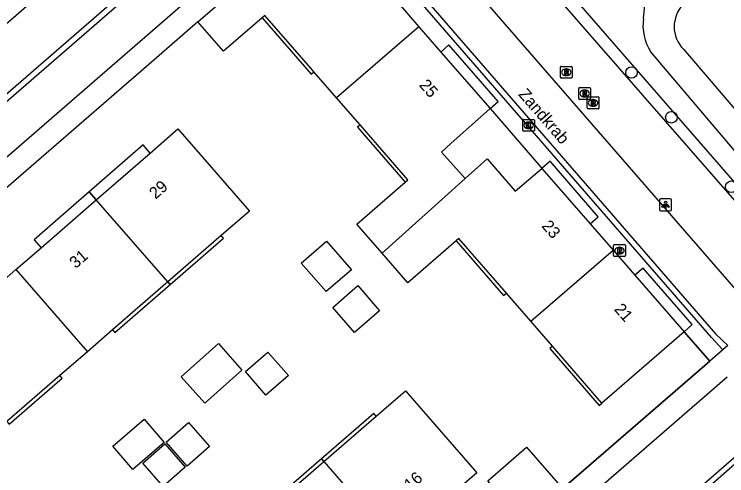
# Model space of a CAD drawing. Extents: x 155888 to 156864, y 383882 to 384671.
# Drawn here: x 156475 to 156535.1, y 384408.3 to 384447.4 of the extents above; entities that cross this region are included whole.
import ezdxf

# ---------------------------------------------------------------- set-up
doc = ezdxf.new("R2010")
doc.units = 0
for name, color, linetype in [('IMGEO_Boom', 7, 'Continuous'), ('IMGEO_Brandkraan', 7, 'Continuous'), ('IMGEO_Haag', 7, 'Continuous'), ('IMGEO_Kolk', 7, 'Continuous'), ('IMGEO_Lichtpunt', 7, 'Continuous'), ('IMGEO_Muur', 7, 'Continuous'), ('IMGEO_Openbare_ruimte_label', 7, 'Continuous'), ('IMGEO_Pand', 7, 'Continuous'), ('IMGEO_Pand_nummerreeks', 7, 'Continuous'), ('IMGEO_Pand_overbouw', 7, 'Continuous'), ('IMGEO_Rijbaan_lokaal_gesloten', 7, 'Continuous'), ('IMGEO_Rijbaan_lokaal_open', 7, 'Continuous'), ('IMGEO_Rioolput', 7, 'Continuous'), ('IMGEO_Voetpad_gesloten', 7, 'Continuous'), ('IMGEO_Voetpad_halfverhard', 7, 'Continuous'), ('IMGEO_Voetpad_open', 7, 'Continuous')]:
    doc.layers.add(name, color=color, linetype=linetype)

msp = doc.modelspace()

# ---------------------------------------------------------------- linework, layer by layer
at = {"layer": 'IMGEO_Boom'}
for centre in [(156527.094, 384442.431), (156530.461, 384438.646), (156535.524, 384432.768)]:
    msp.add_circle(centre, 0.489, dxfattribs=at)
at = {"layer": 'IMGEO_Brandkraan'}
for p, q in [((156525.649, 384427.874), (156526.501, 384427.874)), ((156525.574, 384426.948), (156525.574, 384427.8)), ((156526.062, 384427.654), (156526.087, 384427.654)), ((156526.575, 384427.8), (156526.575, 384426.948)), ((156526.501, 384426.874), (156525.649, 384426.874)), ((156526.085, 384427.094), (156526.06, 384427.094))]:
    msp.add_line(p, q, dxfattribs=at)
for points in [[(156525.649, 384427.874), (156526.501, 384427.874)], [(156525.574, 384426.948), (156525.574, 384427.8)], [(156525.922, 384427.574), (156525.922, 384427.174), (156526.135, 384427.174)], [(156526.153, 384427.574), (156525.922, 384427.574)], [(156526.101, 384427.493), (156526.047, 384427.493), (156526.047, 384427.417)], [(156526.047, 384427.417), (156526.1, 384427.417)], [(156526.109, 384427.341), (156526.047, 384427.341), (156526.047, 384427.26)], [(156526.575, 384427.8), (156526.575, 384426.948)], [(156526.501, 384426.874), (156525.649, 384426.874)], [(156526.047, 384427.26), (156526.109, 384427.26)]]:
    msp.add_lwpolyline(points, dxfattribs=at)
for centre, radius, start, end in [((156525.651, 384427.798), 0.0765, 91.55205, 178.44795), ((156525.651, 384427.798), 0.0765, 91.55205, 178.44795), ((156526.499, 384427.798), 0.0765, 1.55205, 88.44795), ((156526.499, 384427.798), 0.0765, 1.55205, 88.44795), ((156526.102, 384427.455), 0.0379, 267.82845, 90.93552), ((156526.11, 384427.3), 0.0404, 269.87594, 90.50774), ((156526.157, 384427.429), 0.145, 59.4692, 91.53667), ((156526.182, 384427.476), 0.0922, 285.51372, 58.15012), ((156526.187, 384427.284), 0.105, 301.31148, 78.98903), ((156525.651, 384426.95), 0.0765, 181.55205, 268.44795), ((156525.651, 384426.95), 0.0765, 181.55205, 268.44795), ((156526.141, 384427.425), 0.251, 268.66757, 293.53466), ((156526.499, 384426.95), 0.0765, 271.55205, 358.44795), ((156526.499, 384426.95), 0.0765, 271.55205, 358.44795)]:
    msp.add_arc(centre, radius, start, end, dxfattribs=at)
for centre, major_axis, ratio, start_param, end_param in [((156526.061, 384427.374), (-0.387, 0.002), 0.722429, 4.712389, 7.853982), ((156526.086, 384427.374), (-0.39, 0.002), 0.717154, 1.570796, 4.712389)]:
    msp.add_ellipse(centre, major_axis=major_axis, ratio=ratio, start_param=start_param, end_param=end_param, dxfattribs=at)
at = {"layer": 'IMGEO_Haag'}
msp.add_lwpolyline([(156541.642, 384424.916), (156508.804, 384462.59)], dxfattribs=at)
at = {"layer": 'IMGEO_Kolk'}
for p, q in [((156517.903, 384437.539), (156517.903, 384438.391)), ((156517.978, 384438.465), (156518.83, 384438.465)), ((156518.391, 384438.245), (156518.416, 384438.245)), ((156518.904, 384438.391), (156518.904, 384437.539)), ((156518.414, 384437.685), (156518.389, 384437.685)), ((156518.83, 384437.465), (156517.978, 384437.465))]:
    msp.add_line(p, q, dxfattribs=at)
for points in [[(156517.903, 384437.539), (156517.903, 384438.391)], [(156517.978, 384438.465), (156518.83, 384438.465)], [(156518.224, 384438.165), (156518.347, 384438.165), (156518.347, 384438.014), (156518.477, 384438.165), (156518.641, 384438.165), (156518.495, 384438.014), (156518.648, 384437.765), (156518.496, 384437.765), (156518.411, 384437.929), (156518.347, 384437.862), (156518.347, 384437.765), (156518.224, 384437.765), (156518.224, 384438.165)], [(156518.904, 384438.391), (156518.904, 384437.539)], [(156518.83, 384437.465), (156517.978, 384437.465)]]:
    msp.add_lwpolyline(points, dxfattribs=at)
for centre, start, end in [((156517.98, 384438.389), 91.55205, 178.44795), ((156517.98, 384438.389), 91.55205, 178.44795), ((156518.828, 384438.389), 1.55205, 88.44795), ((156518.828, 384438.389), 1.55205, 88.44795), ((156517.98, 384437.541), 181.55205, 268.44795), ((156517.98, 384437.541), 181.55205, 268.44795), ((156518.828, 384437.541), 271.55205, 358.44795), ((156518.828, 384437.541), 271.55205, 358.44795)]:
    msp.add_arc(centre, 0.0765, start, end, dxfattribs=at)
for centre, major_axis, ratio, start_param, end_param in [((156518.39, 384437.965), (-0.387, 0.002), 0.722429, 4.712389, 7.853982), ((156518.415, 384437.965), (-0.39, 0.002), 0.717154, 1.570796, 4.712389)]:
    msp.add_ellipse(centre, major_axis=major_axis, ratio=ratio, start_param=start_param, end_param=end_param, dxfattribs=at)
at = {"layer": 'IMGEO_Lichtpunt'}
for p, q in [((156529.469, 384431.643), (156529.469, 384430.836)), ((156529.469, 384431.643), (156529.469, 384430.836)), ((156530.371, 384431.738), (156529.563, 384431.738)), ((156530.371, 384431.738), (156529.563, 384431.738)), ((156530.465, 384430.836), (156530.465, 384431.643)), ((156530.465, 384430.836), (156530.465, 384431.643)), ((156529.563, 384430.742), (156530.371, 384430.742)), ((156529.563, 384430.742), (156530.371, 384430.742))]:
    msp.add_line(p, q, dxfattribs=at)
for points in [[(156529.843, 384431.307), (156529.882, 384431.279), (156529.694, 384431.017), (156529.656, 384431.044), (156529.843, 384431.307)], [(156529.945, 384431.259), (156529.992, 384431.259), (156529.992, 384430.937), (156529.945, 384430.937), (156529.945, 384431.259)], [(156530.055, 384431.279), (156530.093, 384431.306), (156530.28, 384431.044), (156530.241, 384431.016), (156530.055, 384431.279)]]:
    msp.add_lwpolyline(points, dxfattribs=at)
msp.add_circle((156529.968, 384431.441), 0.0994, dxfattribs=at)
for centre, start, end in [((156529.563, 384431.643), 90, 180), ((156529.563, 384431.643), 90, 180), ((156530.371, 384431.643), 0, 90), ((156530.371, 384431.643), 0, 90), ((156529.563, 384430.836), 180, 270), ((156529.563, 384430.836), 180, 270), ((156530.371, 384430.836), 270, 0), ((156530.371, 384430.836), 270, 360)]:
    msp.add_arc(centre, 0.0946, start, end, dxfattribs=at)
at = {"layer": 'IMGEO_Muur'}
for points in [[(156490.462, 384446.708), (156485.017, 384441.983)], [(156531.539, 384420.513), (156533.705, 384418.024)], [(156533.705, 384418.024), (156517.626, 384404.097)]]:
    msp.add_lwpolyline(points, dxfattribs=at)
at = {"layer": 'IMGEO_Pand'}
for points in [[(156490.462, 384446.708), (156500.942, 384455.803)], [(156500.942, 384455.803), (156503.066, 384453.296), (156507.2, 384448.534), (156509.131, 384446.31)], [(156502.175, 384440.289), (156500.254, 384442.502), (156500, 384442.794), (156496.119, 384447.265), (156495.892, 384447.068), (156492.616, 384444.225), (156490.462, 384446.708)], [(156509.131, 384446.31), (156502.175, 384440.289)], [(156509.131, 384446.31), (156510.994, 384444.164), (156515.141, 384439.387)], [(156506.032, 384427.149), (156503.89, 384429.619), (156507.967, 384433.159), (156508.194, 384433.356), (156504.16, 384438.002), (156502.175, 384440.289)], [(156515.141, 384439.387), (156511.83, 384436.415), (156511.04, 384435.705), (156513.054, 384433.462)], [(156481.878, 384431.663), (156486.437, 384435.625), (156488.776, 384437.658), (156494.811, 384430.714), (156492.441, 384428.654), (156487.916, 384424.721)], [(156513.054, 384433.462), (156514.896, 384435.119), (156517.263, 384432.39), (156519.529, 384434.327)], [(156519.529, 384434.327), (156523.599, 384429.646), (156525.539, 384427.414)], [(156506.032, 384427.149), (156513.054, 384433.462)], [(156475.089, 384425.762), (156477.213, 384427.608), (156481.878, 384431.663)], [(156487.916, 384424.721), (156481.878, 384431.663)], [(156499.199, 384426.321), (156501.333, 384428.172), (156503.43, 384425.753), (156501.296, 384423.902), (156499.199, 384426.321)], [(156518.587, 384421.389), (156516.523, 384423.762), (156512.499, 384428.391), (156512.273, 384428.194), (156508.197, 384424.651), (156506.032, 384427.149)], [(156518.587, 384421.389), (156525.539, 384427.414)], [(156525.539, 384427.414), (156527.383, 384425.294), (156531.539, 384420.513)], [(156468.296, 384419.857), (156472.864, 384423.827), (156475.089, 384425.762)], [(156475.089, 384425.762), (156481.127, 384418.82)], [(156487.916, 384424.721), (156483.247, 384420.663), (156481.127, 384418.82)], [(156503.97, 384424.405), (156505.811, 384422.283), (156503.695, 384420.447), (156501.854, 384422.57), (156503.97, 384424.405)], [(156531.539, 384420.513), (156524.596, 384414.477), (156520.424, 384419.275), (156518.587, 384421.389)], [(156489.061, 384416.705), (156492.194, 384419.501), (156494.185, 384417.269), (156491.052, 384414.474), (156489.061, 384416.705)], [(156481.127, 384418.82), (156478.807, 384416.803), (156474.338, 384412.919)], [(156494.478, 384417.14), (156496.38, 384418.793), (156498.116, 384416.796), (156496.214, 384415.143), (156494.478, 384417.14)], [(156501.098, 384409.523), (156505.528, 384413.372), (156508.001, 384415.52), (156514.033, 384408.573), (156511.693, 384406.541), (156507.129, 384402.575)], [(156483.276, 384410.817), (156485.914, 384413.109), (156487.619, 384411.148), (156484.981, 384408.855), (156483.276, 384410.817)], [(156487.778, 384411.182), (156489.677, 384412.832), (156491.448, 384410.794), (156489.55, 384409.144), (156487.778, 384411.182)], [(156485.814, 384409.399), (156487.677, 384411.019), (156489.39, 384409.047), (156487.527, 384407.428), (156485.814, 384409.399)], [(156518.22, 384410.734), (156521.081, 384407.439), (156517.824, 384404.61), (156514.962, 384407.905), (156518.22, 384410.734)], [(156494.307, 384403.625), (156496.428, 384405.467), (156500, 384408.57), (156501.098, 384409.523)], [(156501.098, 384409.523), (156507.129, 384402.575)]]:
    msp.add_lwpolyline(points, dxfattribs=at)
at = {"layer": 'IMGEO_Pand_overbouw'}
for points in [[(156495.892, 384447.068), (156500.027, 384442.305), (156500.254, 384442.502), (156500, 384442.794), (156496.119, 384447.265)], [(156510.994, 384444.164), (156515.141, 384439.387), (156515.816, 384439.993), (156511.674, 384444.778)], [(156504.16, 384438.002), (156503.937, 384437.801), (156507.967, 384433.159), (156508.194, 384433.356)], [(156481.878, 384431.663), (156486.437, 384435.625), (156485.849, 384436.307), (156481.287, 384432.342)], [(156520.232, 384434.929), (156519.529, 384434.327), (156523.599, 384429.646), (156524.289, 384430.22)], [(156481.878, 384431.663), (156481.287, 384432.342), (156476.622, 384428.288), (156477.213, 384427.608)], [(156487.916, 384424.721), (156488.113, 384424.495), (156492.637, 384428.427), (156492.441, 384428.654)], [(156516.523, 384423.762), (156512.499, 384428.391), (156512.273, 384428.194), (156516.293, 384423.571)], [(156527.383, 384425.294), (156531.539, 384420.513), (156532.206, 384421.107), (156528.07, 384425.888)], [(156483.247, 384420.663), (156483.444, 384420.437), (156488.113, 384424.495), (156487.916, 384424.721)], [(156520.424, 384419.275), (156520.197, 384419.079), (156524.37, 384414.28), (156524.596, 384414.477)], [(156478.807, 384416.803), (156474.338, 384412.919), (156474.535, 384412.693), (156479.001, 384416.574)], [(156501.098, 384409.523), (156505.528, 384413.372), (156505.331, 384413.598), (156500.901, 384409.75)], [(156501.098, 384409.523), (156500.901, 384409.75), (156496.231, 384405.693), (156496.428, 384405.467), (156500, 384408.57)]]:
    msp.add_lwpolyline(points, close=True, dxfattribs=at)
at = {"layer": 'IMGEO_Rijbaan_lokaal_gesloten'}
for points in [[(156426.433, 384399.009), (156427.492, 384399.882), (156435.101, 384405.965), (156436.569, 384407.23), (156500, 384462.343), (156522.19, 384481.631), (156524.469, 384483.595), (156538.047, 384495.41), (156543.317, 384500), (156545.489, 384501.892), (156599.206, 384548.488), (156600.688, 384549.796), (156608.807, 384556.844), (156609.964, 384557.948), (156616.394, 384563.892), (156618.279, 384565.679)], [(156532.718, 384407.227), (156535.755, 384409.872), (156541.065, 384414.476), (156553.428, 384425.242), (156554.199, 384425.889), (156556.634, 384427.993), (156558.595, 384429.695), (156561.013, 384431.799), (156561.818, 384432.506), (156578.374, 384446.985), (156579.274, 384447.734), (156582.636, 384450.593), (156600.213, 384465.85), (156600.98, 384466.526), (156603.356, 384468.573), (156605.316, 384470.305), (156607.771, 384472.443), (156608.606, 384473.149), (156629.369, 384491.187), (156639.517, 384500), (156652.137, 384510.96), (156653.714, 384512.362), (156654.15, 384512.714), (156654.284, 384512.822)], [(156505.192, 384459.454), (156537.928, 384421.705)], [(156429.337, 384395.556), (156437.726, 384403.475), (156439.179, 384404.792), (156499.799, 384457.474)], [(156502.416, 384457.042), (156534.197, 384420.326), (156535.23, 384419.334)], [(156535.175, 384416.658), (156500, 384386.117), (156464.463, 384355.261)]]:
    msp.add_lwpolyline(points, dxfattribs=at)
at = {"layer": 'IMGEO_Rijbaan_lokaal_open'}
for points in [[(156521.889, 384481.979), (156500, 384462.952), (156436.281, 384407.589), (156434.814, 384406.324), (156427.202, 384400.239), (156426.126, 384399.352)], [(156534.81, 384418.964), (156533.853, 384420.021), (156502.058, 384456.731)], [(156535.23, 384419.334), (156534.81, 384418.964)], [(156533.02, 384406.88), (156536.057, 384409.525)]]:
    msp.add_lwpolyline(points, dxfattribs=at)
at = {"layer": 'IMGEO_Rioolput'}
for p, q in [((156521.158, 384442.954), (156522.01, 384442.954)), ((156521.083, 384442.028), (156521.083, 384442.88)), ((156521.571, 384442.734), (156521.596, 384442.734)), ((156522.084, 384442.88), (156522.084, 384442.028)), ((156522.01, 384441.954), (156521.158, 384441.954)), ((156521.594, 384442.174), (156521.569, 384442.174)), ((156522.708, 384441.158), (156523.56, 384441.158)), ((156522.633, 384440.232), (156522.633, 384441.084)), ((156523.121, 384440.938), (156523.146, 384440.938)), ((156523.634, 384441.084), (156523.634, 384440.232)), ((156523.56, 384440.158), (156522.708, 384440.158)), ((156523.144, 384440.378), (156523.119, 384440.378)), ((156523.345, 384439.438), (156523.345, 384440.29)), ((156523.42, 384440.364), (156524.272, 384440.364)), ((156523.833, 384440.144), (156523.858, 384440.144)), ((156524.346, 384440.29), (156524.346, 384439.438)), ((156524.272, 384439.364), (156523.42, 384439.364)), ((156523.856, 384439.584), (156523.831, 384439.584))]:
    msp.add_line(p, q, dxfattribs=at)
for points in [[(156521.158, 384442.954), (156522.01, 384442.954)], [(156521.083, 384442.028), (156521.083, 384442.88)], [(156521.672, 384442.652), (156521.42, 384442.654), (156521.42, 384442.254)], [(156521.42, 384442.254), (156521.544, 384442.254), (156521.544, 384442.416), (156521.555, 384442.416)], [(156521.598, 384442.573), (156521.544, 384442.573), (156521.544, 384442.492)], [(156521.544, 384442.492), (156521.596, 384442.492)], [(156521.602, 384442.387), (156521.673, 384442.254), (156521.813, 384442.254), (156521.748, 384442.38)], [(156522.084, 384442.88), (156522.084, 384442.028)], [(156522.01, 384441.954), (156521.158, 384441.954)], [(156522.708, 384441.158), (156523.56, 384441.158)], [(156522.633, 384440.232), (156522.633, 384441.084)], [(156523.222, 384440.856), (156522.97, 384440.858), (156522.97, 384440.458)], [(156522.97, 384440.458), (156523.094, 384440.458), (156523.094, 384440.62), (156523.105, 384440.62)], [(156523.148, 384440.777), (156523.094, 384440.777), (156523.094, 384440.696)], [(156523.094, 384440.696), (156523.146, 384440.696)], [(156523.152, 384440.591), (156523.223, 384440.458), (156523.363, 384440.458), (156523.298, 384440.584)], [(156523.634, 384441.084), (156523.634, 384440.232)], [(156523.56, 384440.158), (156522.708, 384440.158)], [(156523.345, 384439.438), (156523.345, 384440.29)], [(156523.42, 384440.364), (156524.272, 384440.364)], [(156523.934, 384440.062), (156523.682, 384440.064), (156523.682, 384439.664)], [(156523.86, 384439.983), (156523.806, 384439.983), (156523.806, 384439.902)], [(156523.806, 384439.902), (156523.858, 384439.902)], [(156524.346, 384440.29), (156524.346, 384439.438)], [(156524.272, 384439.364), (156523.42, 384439.364)], [(156523.682, 384439.664), (156523.806, 384439.664), (156523.806, 384439.826), (156523.817, 384439.826)], [(156523.864, 384439.797), (156523.935, 384439.664), (156524.075, 384439.664), (156524.01, 384439.79)]]:
    msp.add_lwpolyline(points, dxfattribs=at)
for centre, radius, start, end in [((156521.16, 384442.878), 0.0765, 91.55205, 178.44795), ((156521.16, 384442.878), 0.0765, 91.55205, 178.44795), ((156522.008, 384442.878), 0.0765, 1.55205, 88.44795), ((156522.008, 384442.878), 0.0765, 1.55205, 88.44795), ((156521.554, 384442.363), 0.0533, 26.02933, 88.69889), ((156521.58, 384442.681), 0.19, 274.7715, 282.96867), ((156521.604, 384442.477), 0.0964, 77.00612, 93.18647), ((156521.618, 384442.534), 0.0378, 276.66336, 79.67722), ((156521.671, 384442.542), 0.109, 350.36119, 89.41601), ((156521.669, 384442.542), 0.112, 277.58423, 350.98172), ((156521.653, 384442.327), 0.108, 29.51342, 73.79051), ((156521.16, 384442.03), 0.0765, 181.55205, 268.44795), ((156521.16, 384442.03), 0.0765, 181.55205, 268.44795), ((156522.008, 384442.03), 0.0765, 271.55205, 358.44795), ((156522.008, 384442.03), 0.0765, 271.55205, 358.44795), ((156522.71, 384441.082), 0.0765, 91.55205, 178.44795), ((156522.71, 384441.082), 0.0765, 91.55205, 178.44795), ((156523.558, 384441.082), 0.0765, 1.55205, 88.44795), ((156523.558, 384441.082), 0.0765, 1.55205, 88.44795), ((156523.104, 384440.567), 0.0533, 26.02933, 88.69889), ((156523.13, 384440.885), 0.19, 274.7715, 282.96867), ((156523.154, 384440.681), 0.0964, 77.00612, 93.18647), ((156523.168, 384440.738), 0.0378, 276.66336, 79.67722), ((156523.221, 384440.746), 0.109, 350.36119, 89.41601), ((156523.219, 384440.746), 0.112, 277.58423, 350.98172), ((156523.203, 384440.531), 0.108, 29.51342, 73.79051), ((156522.71, 384440.234), 0.0765, 181.55205, 268.44795), ((156522.71, 384440.234), 0.0765, 181.55205, 268.44795), ((156523.422, 384440.288), 0.0765, 91.55205, 178.44795), ((156523.422, 384440.288), 0.0765, 91.55205, 178.44795), ((156523.558, 384440.234), 0.0765, 271.55205, 358.44795), ((156523.558, 384440.234), 0.0765, 271.55205, 358.44795), ((156523.842, 384440.091), 0.19, 274.7715, 282.96867), ((156523.866, 384439.887), 0.0964, 77.00612, 93.18647), ((156523.88, 384439.944), 0.0378, 276.66336, 79.67722), ((156523.933, 384439.952), 0.109, 350.36119, 89.41601), ((156523.931, 384439.952), 0.112, 277.58423, 350.98172), ((156524.27, 384440.288), 0.0765, 1.55205, 88.44795), ((156524.27, 384440.288), 0.0765, 1.55205, 88.44795), ((156523.422, 384439.44), 0.0765, 181.55205, 268.44795), ((156523.422, 384439.44), 0.0765, 181.55205, 268.44795), ((156523.816, 384439.773), 0.0533, 26.02933, 88.69889), ((156523.915, 384439.737), 0.108, 29.51342, 73.79051), ((156524.27, 384439.44), 0.0765, 271.55205, 358.44795), ((156524.27, 384439.44), 0.0765, 271.55205, 358.44795)]:
    msp.add_arc(centre, radius, start, end, dxfattribs=at)
for centre, major_axis, ratio, start_param, end_param in [((156521.57, 384442.454), (-0.387, 0.002), 0.722429, 4.712389, 7.853982), ((156521.595, 384442.454), (-0.39, 0.002), 0.717154, 1.570796, 4.712389), ((156523.12, 384440.658), (-0.387, 0.002), 0.722429, 4.712389, 7.853982), ((156523.145, 384440.658), (-0.39, 0.002), 0.717154, 1.570796, 4.712389), ((156523.832, 384439.864), (-0.387, 0.002), 0.722429, 4.712389, 7.853982), ((156523.857, 384439.864), (-0.39, 0.002), 0.717154, 1.570796, 4.712389)]:
    msp.add_ellipse(centre, major_axis=major_axis, ratio=ratio, start_param=start_param, end_param=end_param, dxfattribs=at)
at = {"layer": 'IMGEO_Voetpad_gesloten'}
for points in [[(156528.096, 384446.994), (156528.249, 384448.478), (156524.292, 384453.084), (156528.323, 384456.572), (156532.461, 384452.079), (156541.761, 384460.356), (156546.011, 384463.994)], [(156538.782, 384433.472), (156536.862, 384434.843), (156535.789, 384435.84), (156528.707, 384444.206)], [(156531.472, 384444.401), (156538.508, 384436.198)]]:
    msp.add_lwpolyline(points, dxfattribs=at)
for centre, radius, start, end in [((156533.433, 384446.31), 2.737, 136.48903, 224.23584), ((156532.236, 384446.44), 4.177, 172.38175, 212.34054)]:
    msp.add_arc(centre, radius, start, end, dxfattribs=at)
at = {"layer": 'IMGEO_Voetpad_halfverhard'}
msp.add_lwpolyline([(156551.048, 384434.507), (156541.675, 384426.397), (156510.324, 384462.492), (156527.668, 384477.588)], dxfattribs=at)
at = {"layer": 'IMGEO_Voetpad_open'}
for points in [[(156426.126, 384399.352), (156423.484, 384402.425), (156426.371, 384404.961), (156500, 384468.928), (156518.931, 384485.374), (156521.889, 384481.979)], [(156490.462, 384446.708), (156485.017, 384441.983), (156484.867, 384441.853), (156430.348, 384394.521)], [(156515.141, 384439.387), (156517.113, 384437.112), (156519.442, 384434.427), (156519.529, 384434.327)], [(156533.705, 384418.024), (156531.539, 384420.513)], [(156534.81, 384418.964), (156533.705, 384418.024)], [(156463.122, 384356.762), (156517.626, 384404.097), (156533.705, 384418.024)]]:
    msp.add_lwpolyline(points, dxfattribs=at)

# ---------------------------------------------------------------- texts
at = {"layer": 'IMGEO_Openbare_ruimte_label'}
msp.add_text('Zandkrab', height=1, rotation=310.78157, dxfattribs=at).set_placement((156517.481, 384440.558))
at = {"layer": 'IMGEO_Pand_nummerreeks'}
for s, rotation, p in [('25', 310.96054, (156509.104, 384441.338)), ('29', 40.9966, (156486.888, 384431.673)), ('23', 311.00638, (156519.45, 384429.421)), ('31', 40.9966, (156480.144, 384425.81)), ('21', 311.00409, (156525.572, 384422.378)), ('16', 40.97993, (156508.409, 384407.026))]:
    msp.add_text(s, height=1, rotation=rotation, dxfattribs=at).set_placement(p)

doc.saveas('drawing.dxf')
